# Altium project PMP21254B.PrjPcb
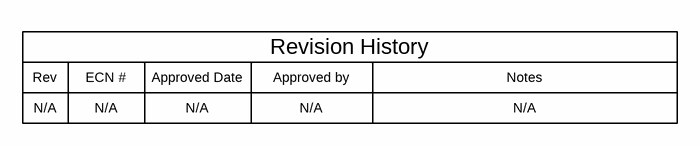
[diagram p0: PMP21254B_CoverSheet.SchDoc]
CopyrightYear: 2021; EVM_orderable: no; PCB_Layout: Josh Mandelcorn; PCB_Rev: B; PRJ_Customer: Public Release; PRJ_Engineer: Josh Mandelcorn; PRJ_Number: PMP21254; PRJ_Title: TPS546D24A 4 Phases Compact Design; SCH_Rev: B; TechSupport: http://www.ti.com/support; TID: N/A
3 sheets, 206 parts. Net scope: flat (ports and power ports of the same name join across sheets).
Board file: PMP21254B_PCB.PcbDoc
Sheets:
  PMP21254B_CoverSheet.SchDoc
  PMP21254B_Leader&Aux.SchDoc
  PMP21254B_Followers&Hardware.SchDoc

## Sheet PMP21254B_CoverSheet.SchDoc
size 431 x 279 mm; Date: Not shown in title block; ApprovedBy: Not shown in title block; CheckedBy: Not shown in title block; Author: Not shown in title block; CompanyName: Not shown in title block; Engineer: Not shown in title block; Organization: Not shown in title block; Address1: Not shown in title block; Address2: Not shown in title block; Address3: Not shown in title block; Address4: Not shown in title block; DocumentNumber: 1; Revision: Use project parameter SCH_Rev; SheetNumber: 1; SheetTotal: 3; PageSetup: Record=PageOptions¦CenterHorizontal=True¦CenterVertical=True¦PrintScale=1.00¦XCorrection=1.00¦YCorrection=1.00¦PrintKind=0¦BorderSize=5000000¦LeftOffset=0¦BottomOffset=0¦Orientation=2¦PaperLength=1000¦PaperWidth=1000¦Scale=100¦PaperSource=15¦PrintQuality=600¦MediaType=1¦DitherType=10¦PaperKind=Letter¦PrintScaleMode=1

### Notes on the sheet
- Rev
- N/A
- ECN #
- Approved Date
- Approved by
- Revision History
- Notes

## Sheet PMP21254B_Leader&Aux.SchDoc
size 431 x 279 mm; Date: Not shown in title block; ApprovedBy: Not shown in title block; CheckedBy: Not shown in title block; Author: Not shown in title block; CompanyName: Not shown in title block; Engineer: Not shown in title block; Organization: Not shown in title block; Address1: Not shown in title block; Address2: Not shown in title block; Address3: Not shown in title block; Address4: Not shown in title block; DocumentNumber: 1; Revision: Use project parameter SCH_Rev; SheetNumber: 2; SheetTotal: 3; PageSetup: Record=PageOptions¦CenterHorizontal=True¦CenterVertical=True¦PrintScale=1.00¦XCorrection=1.00¦YCorrection=1.00¦PrintKind=0¦BorderSize=5000000¦LeftOffset=0¦BottomOffset=0¦Orientation=2¦PaperLength=1000¦PaperWidth=1000¦Scale=100¦PaperSource=15¦PrintQuality=600¦MediaType=1¦DitherType=10¦PaperKind=Letter¦PrintScaleMode=1
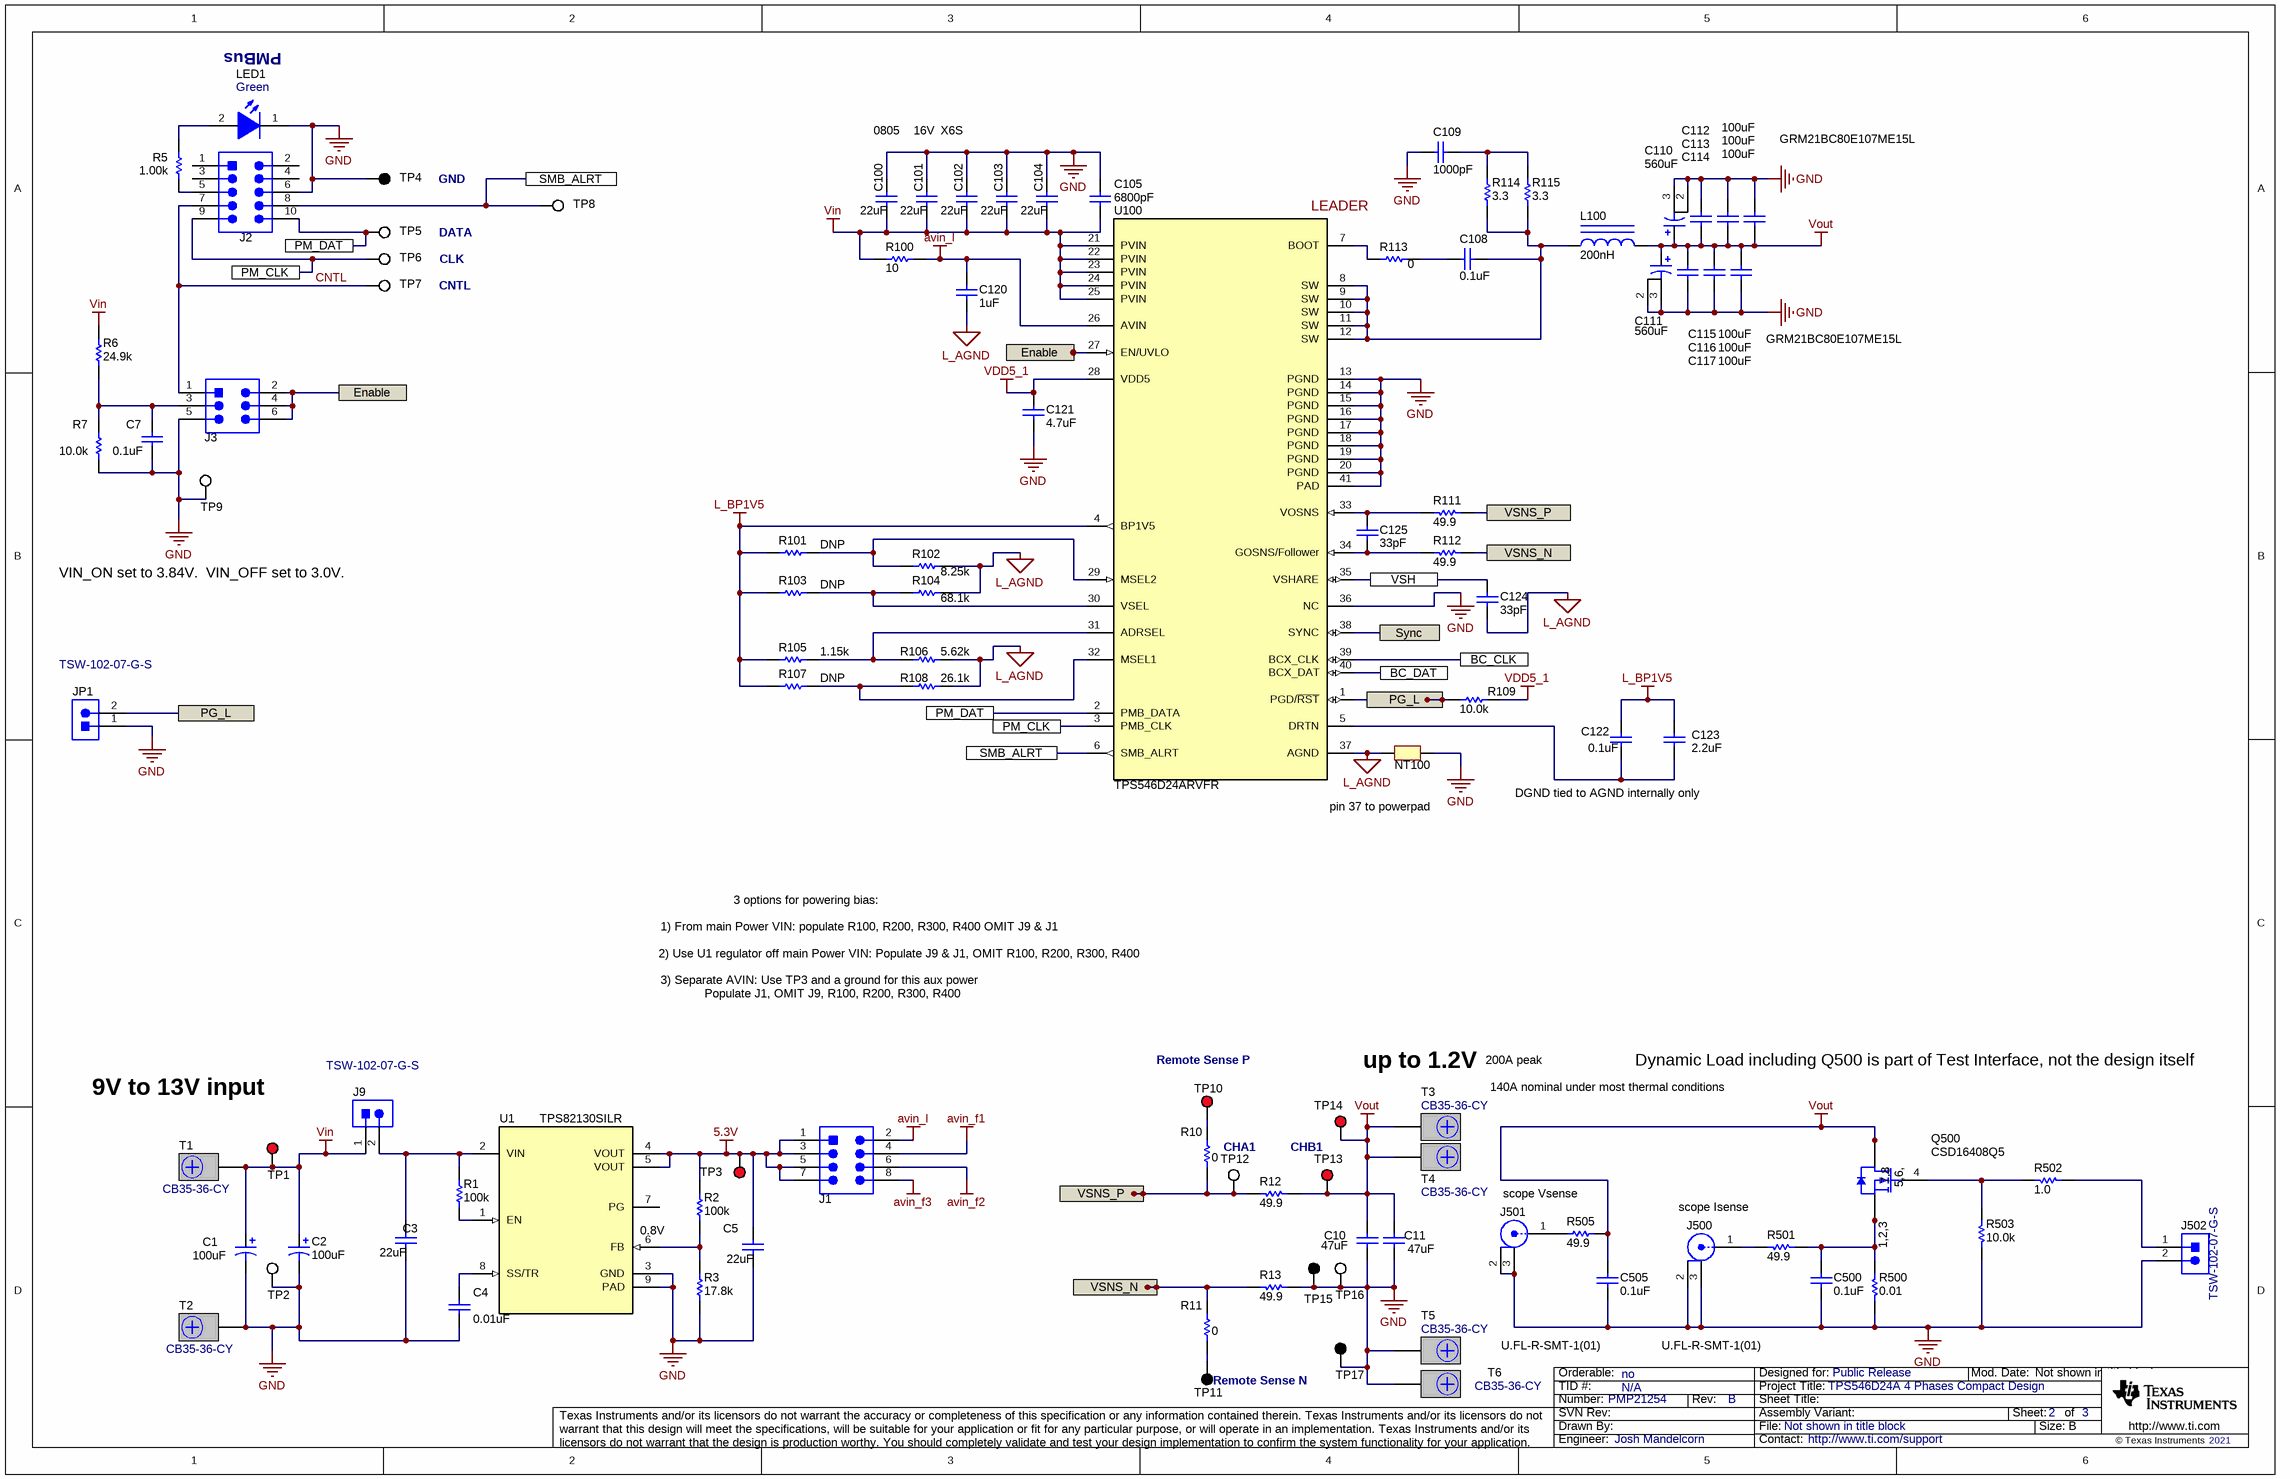
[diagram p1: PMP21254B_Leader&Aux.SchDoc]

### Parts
C1  ValueDisplayed: 100uF  [SM_RADIAL_G]  (hidden comment: Cap_Polarized)
C2  ValueDisplayed: 100uF  [SM_RADIAL_G]  (hidden comment: Cap_Polarized)
C3  value 22uF  [0805]  (hidden comment: Capacitor)
C4  ValueDisplayed: 0.01uF  [0402]  (hidden comment: C0402C103J5RACTU)
C5  value 22uF  [0805]  (hidden comment: Capacitor)
C7  ValueDisplayed: 0.1uF  [0402_065]  (hidden comment: Capacitor)
C10  ValueDisplayed: 47uF  [1210_270]  (hidden comment: Capacitor)
C11  ValueDisplayed: 47uF  [1210_270]  (hidden comment: Capacitor)
C100  value 22uF  [0805]  (hidden comment: Capacitor)
C101  value 22uF  VDC_V: 16V  TempCo: X6S  [0805]  (hidden comment: Capacitor)
C102  value 22uF  [0805]  (hidden comment: Capacitor)
C103  value 22uF  [0805]  (hidden comment: Capacitor)
C104  value 22uF  [0805]  (hidden comment: Capacitor)
C105  ValueDisplayed: 6800pF  [0402]  (hidden comment: Capacitor)
C108  ValueDisplayed: 0.1uF  [0402_065]  (hidden comment: Capacitor)
C109  ValueDisplayed: 1000pF  [0603L]  (hidden comment: Capacitor)
C110  ValueDisplayed: 560uF  [GX_3TERM]  (hidden comment: CAPP_POS1NEG23)
C111  ValueDisplayed: 560uF  [GX_3TERM]  (hidden comment: CAPP_POS1NEG23)
C112  ValueDisplayed: 100uF  [0805]  (hidden comment: Capacitor)
C113  ValueDisplayed: 100uF  [0805]  (hidden comment: Capacitor)
C114  ValueDisplayed: 100uF  [0805]  (hidden comment: Capacitor)
C115  ValueDisplayed: 100uF  [0805]  (hidden comment: Capacitor)
C116  ValueDisplayed: 100uF  [0805]  (hidden comment: Capacitor)
C117  ValueDisplayed: 100uF  [0805]  (hidden comment: Capacitor)
C120  ValueDisplayed: 1uF  [0603L]  (hidden comment: Capacitor)
C121  ValueDisplayed: 4.7uF  [0603]  (hidden comment: Capacitor)
C122  ValueDisplayed: 0.1uF  [0402_065]  (hidden comment: Capacitor)
C123  ValueDisplayed: 2.2uF  [0603L]  (hidden comment: Capacitor)
C124  ValueDisplayed: 33pF  [0402]  (hidden comment: Capacitor)
C125  ValueDisplayed: 33pF  [0402]  (hidden comment: Capacitor)
C500  ValueDisplayed: 0.1uF  [0402]  (hidden comment: Capacitor)
C505  ValueDisplayed: 0.1uF  [0402]  (hidden comment: Capacitor)
J1  Header_4x2  [CONN_PEC04DAAN]  (value not drawn)
J2  Header_5x2  [CONN_5103308-1]  (value not drawn)
J3  Header_3x2  [Sullins_PBC03DAAN]  (value not drawn)
J9  TSW-102-07-G-S  [TSW-102-07-G-S]
J500  U.FL-R-SMT-1(01)  [CONN_UFL-R-SMT-1]
J501  U.FL-R-SMT-1(01)  [CONN_UFL-R-SMT-1]
J502  TSW-102-07-G-S  [TSW-102-07-G-S]
JP1  TSW-102-07-G-S  [TSW-102-07-G-S]
L100  ValueDisplayed: 200nH  [SLC1480]  (hidden comment: SLC1480-201MLB)
LED1  value Green  [WL-SMCW_GREEN]  (hidden comment: 150060GS75000)
NT100  Net-Tie  [Net-Tie_10mil]  (value not drawn)  (net tie, no BOM)
Q500  CSD16408Q5  [DQH0008A]
R1  ValueDisplayed: 100k  [0402]  (hidden comment: ERJ-2RKF1003X)
R2  ValueDisplayed: 100k  [0402]  (hidden comment: ERJ-2RKF1003X)
R3  ValueDisplayed: 17.8k  [0402]  (hidden comment: CRCW040217K8FKED)
R5  ValueDisplayed: 1.00k  [0402]  (hidden comment: RC0402FR-071KL)
R6  ValueDisplayed: 24.9k  [0402]  (hidden comment: CRCW040224K9FKED)
R7  ValueDisplayed: 10.0k  [0402]  (hidden comment: RC0402FR-0710KL)
R10  ValueDisplayed: 0  [0402]  (hidden comment: CRCW04020000Z0ED)
R11  ValueDisplayed: 0  [0402]  (hidden comment: CRCW04020000Z0ED)
R12  ValueDisplayed: 49.9  [0402]  (hidden comment: Resistor)
R13  ValueDisplayed: 49.9  [0402]  (hidden comment: Resistor)
R100  ValueDisplayed: 10  [0402]  (hidden comment: CRCW040210R0JNED)
R101  ValueDisplayed: DNP  [0402]  (hidden comment: Resistor)
R102  ValueDisplayed: 8.25k  [0402]  (hidden comment: Resistor)
R103  ValueDisplayed: DNP  [0402]  (hidden comment: Resistor)
R104  ValueDisplayed: 68.1k  [0402]  (hidden comment: Resistor)
R105  ValueDisplayed: 1.15k  [0402]  (hidden comment: Resistor)
R106  ValueDisplayed: 5.62k  [0402]  (hidden comment: Resistor)
R107  ValueDisplayed: DNP  [0402]  (hidden comment: Resistor)
R108  ValueDisplayed: 26.1k  [0402]  (hidden comment: Resistor)
R109  ValueDisplayed: 10.0k  [0402]  (hidden comment: Resistor)
R111  ValueDisplayed: 49.9  [0402]  (hidden comment: Resistor)
R112  ValueDisplayed: 49.9  [0402]  (hidden comment: Resistor)
R113  ValueDisplayed: 0  [0402]  (hidden comment: Resistor)
R114  ValueDisplayed: 3.3  [0805]  (hidden comment: Resistor)
R115  ValueDisplayed: 3.3  [0805]  (hidden comment: Resistor)
R500  ValueDisplayed: 0.01  [2512]  (hidden comment: Resistor)
R501  ValueDisplayed: 49.9  [0402]  (hidden comment: Resistor)
R502  ValueDisplayed: 1.0  [0402]  (hidden comment: Resistor)
R503  ValueDisplayed: 10.0k  [0402]  (hidden comment: Resistor)
R505  ValueDisplayed: 49.9  [0402]  (hidden comment: Resistor)
T1  CB35-36-CY  [CB35-36-CY]
T2  CB35-36-CY  [CB35-36-CY]
T3  CB35-36-CY  [CB35-36-CY]
T4  CB35-36-CY  [CB35-36-CY]
T5  CB35-36-CY  [CB35-36-CY]
T6  CB35-36-CY  [CB35-36-CY]
TP1  5000  [Keystone5000]  (value not drawn)
TP2  5016  [Testpoint_Keystone_Compact]  (value not drawn)
TP3  5000  [Keystone5000]  (value not drawn)
TP4  5011  [Keystone5011]  (value not drawn)
TP5  5012  [Keystone5012]  (value not drawn)
TP6  5012  [Keystone5012]  (value not drawn)
TP7  5012  [Keystone5012]  (value not drawn)
TP8  5012  [Keystone5012]  (value not drawn)
TP9  5016  [Testpoint_Keystone_Compact]  (value not drawn)
TP10  5010  [Keystone5010]  (value not drawn)
TP11  5011  [Keystone5011]  (value not drawn)
TP12  5012  [Keystone5012]  (value not drawn)
TP13  5010  [Keystone5010]  (value not drawn)
TP14  5010  [Keystone5010]  (value not drawn)
TP15  5011  [Keystone5011]  (value not drawn)
TP16  5016  [Testpoint_Keystone_Compact]  (value not drawn)
TP17  5001  [Keystone5001]  (value not drawn)
U1  TPS82130SILR  [SIL0008D_SMD]
U100  TPS546D24ARVFR  [RVF0040A_SMD_NV]

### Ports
BC_CLK, BC_DAT, Enable, PG_L, PM_CLK, PM_DAT, SMB_ALRT, Sync, VSH, VSNS_N, VSNS_P

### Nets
5.3V: C5.1 J1.1 J1.3 J1.5 J1.7 R2.2 TP3.1 U1.4(VOUT) U1.5(VOUT)
avin_f1: J1.4
avin_f2: J1.6
avin_f3: J1.8
avin_l: C120.1 J1.2 R100.2 U100.26(AVIN)
GND: C1.2(-) C2.2(-) C3.2 C4.2 C5.2 C7.1 C10.1 C11.1 C100.1 C101.1 C102.1 C103.1 C104.1 C105.2 C109.2 C110.2(-) C110.3(-) C111.2(-) C111.3(-) C112.2 C113.2 C114.2 C115.2 C116.2 C117.2 C121.1 C500.2 C505.2 J2.6 J3.5 J500.2 J500.3 J501.2 J501.3 J502.2 JP1.1 LED1.1(K) NT100.2 R3.1 R7.1 R13.1 R500.1 R503.1 T2.1 T5.1 T6.1 TP2.1 TP4.1 TP9.1 TP15.1 TP16.1 TP17.1 U1.3(GND) U1.9(PAD) U100.13(PGND) U100.14(PGND) U100.15(PGND) U100.16(PGND) U100.17(PGND) U100.18(PGND) U100.19(PGND) U100.20(PGND) U100.36(NC) U100.41(PAD)
L_AGND: C120.2 C124.2 NT100.1 R102.2 R104.2 R106.2 R108.2 U100.37(AGND)
L_BP1V5: C122.1 C123.1 R101.1 R103.1 R105.1 R107.1 U100.4(BP1V5)
VDD5_1: C121.2 R109.1 U100.28(VDD5)
Vin: C1.1(+) C2.1(+) C100.2 C101.2 C102.2 C103.2 C104.2 C105.1 J9.1 R6.2 R100.1 T1.1 TP1.1 U100.21(PVIN) U100.22(PVIN) U100.23(PVIN) U100.24(PVIN) U100.25(PVIN)
Vout: C10.2 C11.2 C110.1(+) C111.1(+) C112.1 C113.1 C114.1 C115.1 C116.1 C117.1 C505.1 L100.2 Q500.5(D) Q500.6(D) Q500.7(D) Q500.8(D) Q500.9(D) R12.1 R505.2 T3.1 T4.1 TP13.1 TP14.1
BC_CLK: U100.39(BCX_CLK) ; port BC_CLK
BC_DAT: U100.40(BCX_DAT) ; port BC_DAT
CNTL: J2.7 J3.1 TP7.1
Enable: J3.2 J3.4 J3.6 U100.27(EN/UVLO) ; port Enable
PG_L: JP1.2 R109.2 U100.1(PGD/~{RST}) ; port PG_L
PM_CLK: J2.9 TP6.1 U100.3(PMB_CLK) ; port PM_CLK
PM_DAT: J2.10 TP5.1 U100.2(PMB_DATA) ; port PM_DAT
SMB_ALRT: J2.8 TP8.1 U100.6(SMB_ALRT) ; port SMB_ALRT
Sync: U100.38(SYNC) ; port Sync
VSH: C124.1 U100.35(VSHARE) ; port VSH
VSNS_N: R11.2 R13.2 R112.1 ; port VSNS_N
VSNS_P: R10.1 R12.2 R111.1 TP12.1 ; port VSNS_P
NetC3_1: C3.1 J9.2 R1.2 U1.2(VIN)
NetC4_1: C4.1 U1.8(SS/TR)
NetC7_2: C7.2 J3.3 R6.1 R7.2
NetC108_1: C108.1 R113.1
NetC108_2: C108.2 L100.1 R114.1 R115.1 U100.8(SW) U100.9(SW) U100.10(SW) U100.11(SW) U100.12(SW)
NetC109_1: C109.1 R114.2 R115.2
NetC122_2: C122.2 C123.2 U100.5(DRTN)
NetC125_1: C125.1 R111.2 U100.33(VOSNS)
NetC125_2: C125.2 R112.2 U100.34(GOSNS/Follower)
NetC500_1: C500.1 Q500.1(S) Q500.2(S) Q500.3(S) R500.2 R501.1
NetJ2_5: J2.5 R5.1
NetJ500_1: J500.1 R501.2
NetJ501_1: J501.1 R505.1
NetJ502_1: J502.1 R502.1
NetLED1_2: LED1.2(A) R5.2
NetQ500_4: Q500.4(G) R502.2 R503.2
NetR1_1: R1.1 U1.1(EN)
NetR2_1: R2.1 R3.2 U1.6(FB)
NetR10_2: R10.2 TP10.1
NetR11_1: R11.1 TP11.1
NetR101_2: R101.2 R102.1 U100.29(MSEL2)
NetR103_2: R103.2 R104.1 U100.30(VSEL)
NetR105_2: R105.2 R106.1 U100.31(ADRSEL)
NetR107_2: R107.2 R108.1 U100.32(MSEL1)
NetR113_2: R113.2 U100.7(BOOT)

Not connected (* = marked no-connect by the designer): J2 1 2 3 4; U1 7(PG)

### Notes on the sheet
- PMBus
- GRM21BC80E107ME15L
- GND
- DATA
- LEADER
- CLK
- CNTL
- VIN_ON set to 3.84V.  VIN_OFF set to 3.0V.
- pin 37 to powerpad
- DGND tied to AGND internally only
- 3 options for powering bias:
- 1) From main Power VIN: populate R100, R200, R300, R400 OMIT J9 & J1
- 2) Use U1 regulator off main Power VIN: Populate J9 & J1, OMIT R100, R200, R300, R400
- 3) Separate AVIN: Use TP3 and a ground for this aux power
- Populate J1, OMIT J9, R100, R200, R300, R400
- 9V to 13V input
- (near TP10) Remote Sense P
- up to 1.2V
- 200A peak
- 140A nominal under most thermal conditions
- Dynamic Load including Q500 is part of Test Interface, not the design itself
- CHA1
- CHB1
- (near U1) 0.8V
- scope Vsense
- scope Isense
- (near TP11) Remote Sense N

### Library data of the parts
C1 C2 = CMP-0010663-1: CAP, AL, 100 uF, 35 V, +/- 20%, 0.15 ohm, SMD; PartNumber: EEE-FC1V101P; Manufacturer: Panasonic; Polarized: Y; CompType: Capacitor; Value: 100uF; U/M: EA; Cap_F: 100µF; ESR_ohm: 1.5d; VDC_V: 35V; IRMS_A: 2.2dA; TaMin_C: -40°C; TaMax_C: 105°C; Cap_Case: G; AEC Category: Q200; SizeArea_mm2: 123.6; SizeAreaWB_mm2: 172.2; SizeX_mm: 12; SizeY_mm: 10.3; SizeZ_mm: 10.2
C3 C5 C100 C102-C104 = CMP-0007852-1: CAP, CERM, 22 uF, 16 V, +/- 20%, X6S, 0805; PartNumber: C2012X6S1C226M125AC; Manufacturer: TDK; Polarized: N; U/M: EA; Cap_F: 22µF; ESR_ohm: 2.05m; Value1: 0.00205 ohm; VDC_V: 16V; IRMS_A: 4.55587A; TaMin_C: -55°C; TaMax_C: 105°C; SizeArea_mm2: 2.5; SizeAreaWB_mm2: 6.75; SizeX_mm: 2; SizeY_mm: 1.25; SizeZ_mm: 1.45; AEC Category: Q200
C4 = CMP-0006236-2: CAP, CERM, 0.01 uF, 50 V, +/- 5%, X7R, 0402; Manufacturer: Kemet; TaMin_C: -55°C; Polarized: N; SizeAreaWB_mm2: 3; Value1: Unknown; U/M: EA; Value: 0.01uF; TaMax_C: 125°C; SizeZ_mm: 0.6; SizeX_mm: 1; SizeY_mm: 0.5; Value2: 50V; CompType: Capacitor; Cap_F: 10nF; AEC Category: Q200
C7 C108 C122 = CMP-0006204-2: CAP, CERM, 0.1 uF, 16 V, +/- 10%, X5R, 0402; PartNumber: 160R07X104KV4T; Manufacturer: Johanson Technology; Polarized: N; Value: 0.1uF; U/M: EA; Cap_F: 100nF; Value1: Unknown; VDC_V: 16V; TaMin_C: -55°C; TaMax_C: 85°C; Cap_Case: 0402; SizeArea_mm2: 0.5; SizeAreaWB_mm2: 3; SizeX_mm: 1; SizeZ_mm: 0.65; AEC Category: Q200
C10 C11 = CMP-0009220-2: CAP, CERM, 47 uF, 10 V, +/- 10%, X7R, 1210; PartNumber: GRM32ER71A476KE15L; Manufacturer: MuRata; U/M: EA; Cap_F: 47µF; Value: 47uF; Value1: Unknown; VDC_V: 10V; TaMin_C: -55°C; TaMax_C: 125°C; Polarized: N; Cap_Case: 1210; SizeArea_mm2: 8; SizeAreaWB_mm2: 14.7; SizeX_mm: 3.2; SizeY_mm: 2.5; SizeZ_mm: 2.7; AEC Category: Q200
C101 = CMP-0007852-1: CAP, CERM, 22 uF, 16 V, +/- 20%, X6S, 0805; PartNumber: C2012X6S1C226M125AC; Manufacturer: TDK; Polarized: N; U/M: EA; Cap_F: 22µF; ESR_ohm: 2.05m; Value1: 0.00205 ohm; IRMS_A: 4.55587A; TaMin_C: -55°C; TaMax_C: 105°C; SizeArea_mm2: 2.5; SizeAreaWB_mm2: 6.75; SizeX_mm: 2; SizeY_mm: 1.25; SizeZ_mm: 1.45; AEC Category: Q200
C105 = CMP-0006696-2: CAP, CERM, 6800 pF, 50 V, +/- 10%, X7R, 0402; PartNumber: GRM155R71H682KA88D; Manufacturer: MuRata; Polarized: N; Value: 6800pF; U/M: EA; Cap_F: 6.8nF; Value1: Unknown; VDC_V: 50V; TaMin_C: -55°C; TaMax_C: 125°C; AEC Category: Q200; SizeArea_mm2: 0.5; SizeAreaWB_mm2: 3; SizeX_mm: 1; SizeZ_mm: 0.6
C109 = CMP-0006723-4: CAP, CERM, 1000 pF, 100 V, +/- 5%, X7R, 0603; PartNumber: 06031C102JAT2A; Manufacturer: AVX; Polarized: N; Value: 1000pF; U/M: EA; Cap_F: 1nF; ESR_ohm: 2.76d; Value1: 0.276 ohm; VDC_V: 100V; TaMin_C: -55°C; TaMax_C: 125°C; Cap_Case: 0603; AEC Category: Q200; SizeArea_mm2: 1.28; SizeAreaWB_mm2: 4.68; SizeX_mm: 1.6; SizeY_mm: 0.8; SizeZ_mm: 1
C110 C111 = CMP-0012239-3: CAP, Aluminum Polymer, 560 uF, 2 V, +/- 20%, 0.003 ohm, SMD_7.3x1.9x4.3mm SMD; Manufacturer: Panasonic; PartNumber: EEF-GX0D561L; CompType: Capacitor; Value: 560uF; Polarized: Y; Cap_F: 560µF; VDC_V: 2V; ESR_ohm: 3m; IRMS_A: 4A; TaMin_C: -40°C; TaMax_C: 105°C; Cap_Case: D; SizeAreaWB_mm2: 58.59; SizeArea_mm2: 31.39; SizeX_mm: 7.3; SizeY_mm: 4.3; SizeZ_mm: 2; AEC Category: Q200; AEC Qualified: N
C112-C117 = CMP-0008277-2: CAP, CERM, 100 uF, 4 V, +/- 20%, X5R, 0805; PartNumber: GRM21BR60G107ME15L; Manufacturer: MuRata; U/M: EA; Cap_F: 100µF; Value: 100uF; Value1: Unknown; VDC_V: 4V; TaMin_C: -55°C; TaMax_C: 85°C; Polarized: N; SizeArea_mm2: 2.5; SizeAreaWB_mm2: 6.75; SizeX_mm: 2; SizeY_mm: 1.25; SizeZ_mm: 1.45; AEC Category: Q200
C120 = CMP-0007405-4: CAP, CERM, 1 uF, 25 V, +/- 10%, X7R, 0603; PartNumber: GRM188R71E105KA12D; Manufacturer: MuRata; Polarized: N; Value: 1uF; U/M: EA; Cap_F: 1µF; Value1: Unknown; VDC_V: 25V; TaMin_C: -55°C; TaMax_C: 125°C; Cap_Case: 0603; AEC Category: Q200; SizeArea_mm2: 1.28; SizeAreaWB_mm2: 4.68; SizeX_mm: 1.6; SizeY_mm: 0.8; SizeZ_mm: 1
C121 = CMP-0007058-4: CAP, CERM, 4.7 uF, 10 V, +/- 10%, X7S, 0603; PartNumber: C1608X7S1A475K080AC; Manufacturer: TDK; Polarized: N; Value: 4.7uF; U/M: EA; Cap_F: 4.7µF; Value1: Unknown; VDC_V: 10V; TaMin_C: -55°C; TaMax_C: 125°C; SizeArea_mm2: 1.28; SizeAreaWB_mm2: 4.68; SizeX_mm: 1.6; SizeY_mm: 0.8; SizeZ_mm: 1; AEC Category: Q200
C123 = CMP-0007499-4: CAP, CERM, 2.2 uF, 16 V, +/- 10%, X7R, 0603; PartNumber: GRM188Z71C225KE43; Manufacturer: MuRata; Polarized: N; Value: 2.2uF; U/M: EA; Cap_F: 2.2µF; Value1: Unknown; VDC_V: 16V; TaMin_C: -55°C; TaMax_C: 125°C; Cap_Case: 0603; SizeArea_mm2: 1.28; SizeAreaWB_mm2: 4.68; SizeX_mm: 1.6; SizeY_mm: 0.8; SizeZ_mm: 1; AEC Category: Q200
C124 C125 = CMP-0006377-2: CAP, CERM, 33 pF, 25 V, +/- 5%, C0G/NP0, 0402; PartNumber: GRM1555C1E330JA01D; Manufacturer: MuRata; Polarized: N; Value: 33pF; U/M: EA; Value1: Unknown; VDC_V: 25V; TaMin_C: -55°C; TaMax_C: 125°C; SizeArea_mm2: 0.5; SizeAreaWB_mm2: 3; SizeX_mm: 1; SizeZ_mm: 0.6; AEC Category: Q200
C500 = CMP-0006607-2: CAP, CERM, 0.1 uF, 25 V, +/- 10%, X5R, 0402; PartNumber: GRM155R61E104KA87D; Manufacturer: MuRata; Polarized: N; Value: 0.1uF; U/M: EA; Cap_F: 100nF; Value1: Unknown; VDC_V: 25V; TaMin_C: -55°C; TaMax_C: 85°C; AEC Category: Q200; SizeArea_mm2: 0.5; SizeAreaWB_mm2: 3; SizeX_mm: 1; SizeZ_mm: 0.6
C505 = CMP-0006607-2: CAP, CERM, 0.1 uF, 25 V, +/- 10%, X5R, 0402; PartNumber: GRM155R61E104KA87D; Manufacturer: MuRata; Polarized: N; Value: 0.1uF; U/M: EA; Cap_F: 100nF; Value1: Unknown; VDC_V: 25V; TaMin_C: -55°C; TaMax_C: 85°C; SizeArea_mm2: 0.5; SizeAreaWB_mm2: 3; SizeX_mm: 1; SizeZ_mm: 0.6; AEC Category: Q200
J1 = CMP-0054542-2: Header, 100mil, 4x2, Tin, TH; PartNumber: PEC04DAAN; Manufacturer: Sullins Connector Solutions; Pitch_mm: 2.54; Gender: Male; Shrouded: N; Row_Count: 2; Current_A: 3A; Voltage_V: 1.8kV; Cert_UL: Y; Green_Lifecycle: Not Set; Green_REACh: Incomplete
J2 = CMP-0054834-2: Header (shrouded), 100mil, 5x2, Gold, TH; PartNumber: 5103308-1; Manufacturer: TE Connectivity; Green_Lifecycle: Active; Green_REACh: Passed
J3 = CMP-0054565-2: Header, 100mil, 3x2, Gold, TH; PartNumber: PBC03DAAN; Manufacturer: Sullins Connector Solutions; Pitch_mm: 2.54; Gender: Male; Shrouded: N; Row_Count: 2; Current_A: 3A; Voltage_V: 1.8kV; Cert_UL: Y; Green_Lifecycle: Active; Green_REACh: Passed
J9 J502 JP1 = CMP-0075405-3: Header, 100mil, 2x1, Gold, TH; Manufacturer: Samtec; Pitch_mm: 2.54; Gender: Male; Shrouded: N; Row_Count: 1; Current_A: 6.3A; Voltage_V: 550V; Cert_CSA: Y; Green_Lifecycle: Active; Green_REACh: Passed
J500 J501 = CMP-0075320-1: Receptacle, Ultra Miniature Coaxial, Male Pin, 50 ohm, SMT; Manufacturer: Hirose Electric Co. Ltd.; CNHeader: False; Gender: Female; ContactFinish: Gold
L100 = CMP-0060886-1: Inductor, Shielded, Ferrite, 200 nH, 55 A, 0.00015 ohm, SMD; Manufacturer: Coilcraft; Isat: 76A @ 30% inductance drop; Irms: 55A @ 40C rise; Green_Lifecycle: Not Set; SizeAreaWB_mm2: 231.127; DCR_ohm: 150µ; Green_REACh: Incomplete; Value: 200nH; Imax_A: 55A; SizeZ_mm: 8; SizeY_mm: 12.95; SizeArea_mm2: 174.307; AEC Category: Q200; SizeX_mm: 13.46
LED1 = CMP-0002905-2: LED, Green, SMD; Manufacturer: Wurth Elektronik; Type: InGaN; Vf_V: 3.2V; Io_A: 20mA; Tjmax_C: 85°C; Value1: W; Angle: 140
NT100 = CMP-0078142-3: Single point connection between nets.
Q500 = CMP-0000264-1: MOSFET, N-CH, 25 V, 113 A, DQH0008A (VSON-CLIP-8); Manufacturer: Texas Instruments; Alternate Manufacturer: None; U/M: EA; ChType: N; Value: 25V; Value1: 0.005; Rdson45_ohm: 5.4m; Value2: 6.7 nC; QgTyp_nC: 6.7; Vgs_V: 16V; IdsMax_A: 113A; SizeAreaWB_mm2: 56; SizeArea_mm2: 30; SizeX_mm: 6; SizeY_mm: 5; SizeZ_mm: 1.05; AEC Category: Q101
R1 R2 = CMP-0026659-1: RES, 100 k, 1%, 0.1 W, 0402; Manufacturer: Panasonic; Power_W: 100mW; TempCo: 100 ppm/C; U/M: EA; Value: 100k; EIA_Code: E96; SizeX_mm: 1; SizeY_mm: 0.5; SizeZ_mm: 0.6; Value2: 0.1W; VDC_V: 50V; AEC Category: Q200
R3 = CMP-0026051-3: RES, 17.8 k, 1%, 0.063 W, AEC-Q200 Grade 0, 0402; Manufacturer: Vishay-Dale; Power_W: 63mW; TempCo: 100 ppm/C; Value_Code: 17k8; Value: 17.8k; EIA_Code: E96; SizeX_mm: 1; SizeY_mm: 0.5; SizeZ_mm: 0.6; Value2: 0.063W; AEC Qualified: Y; VDC_V: 50V; AEC Category: Q200; AEC Grade: 0
R5 = CMP-0026725-1: RES, 1.00 k, 1%, 0.0625 W, 0402; Manufacturer: Yageo America; Power_W: 62.5mW; TempCo: 100 ppm/C; Value_Code: 1k00; U/M: EA; Value: 1.00k; EIA_Code: E96; Res_ohm: 1k; SizeX_mm: 1; SizeY_mm: 0.5; SizeZ_mm: 0.6; AEC Qualified: N; VDC_V: 50V; AEC Category: Q200
R6 = CMP-0026196-2: RES, 24.9 k, 1%, 0.063 W, AEC-Q200 Grade 0, 0402; Manufacturer: Vishay-Dale; Power_W: 63mW; TempCo: 100 ppm/C; Value_Code: 24k9; Value: 24.9k; EIA_Code: E96; SizeX_mm: 1; SizeY_mm: 0.5; SizeZ_mm: 0.6; Value2: 0.063W; AEC Qualified: Y; VDC_V: 50V; AEC Category: Q200; AEC Grade: 0
R7 = CMP-0078669-1: RES, 10.0 k, 1%, 0.063 W, 0402; Manufacturer: Yageo America; Power_W: 63mW; Green_Lifecycle: Active; TempCo: 100 ppm/C; Value_Code: 10k0; Green_REACh: Passed; Value: 10.0k; EIA_Code: E96; Res_ohm: 10k; SizeX_mm: 1; SizeY_mm: 0.5; SizeZ_mm: 0.6; Value2: 0.063W; AEC Qualified: N; AEC Category: Q200
R10 R11 = CMP-0026822-3: RES, 0, 5%, 0.063 W, AEC-Q200 Grade 0, 0402; Manufacturer: Vishay-Dale; Power_W: 63mW; TempCo: 200 ppm/C; Value_Code: 0000; Value: 0; EIA_Code: E24; SizeX_mm: 1; SizeY_mm: 0.5; SizeZ_mm: 0.6; Value2: 0.063W; AEC Qualified: Y; VDC_V: 50V; AEC Category: Q200
R12 R13 R111 R112 R501 = CMP-0026404-2: RES, 49.9, 1%, 0.063 W, AEC-Q200 Grade 0, 0402; PartNumber: CRCW040249R9FKED; Manufacturer: Vishay-Dale; Value: 49.9; Value_Code: 49R9; Power_W: 63mW; Value2: 0.063W; VDC_V: 50V; TempCo: 100 ppm/C; EIA_Code: E96; AEC Category: Q200; AEC Qualified: Y; AEC Grade: 0; SizeArea_mm2: 0.5; SizeX_mm: 1; SizeZ_mm: 0.6
R100 = CMP-0026827-3: RES, 10, 5%, 0.063 W, AEC-Q200 Grade 0, 0402; Manufacturer: Vishay-Dale; Power_W: 63mW; TempCo: 200 ppm/C; Value_Code: 10R0; Value: 10; EIA_Code: E24; SizeX_mm: 1; SizeY_mm: 0.5; SizeZ_mm: 0.6; Value2: 0.063W; AEC Qualified: Y; VDC_V: 50V; AEC Category: Q200; AEC Grade: 0
R101-R109 = CMP-0025958-3: RES, 10.0 k, 1%, 0.063 W, AEC-Q200 Grade 0, 0402; PartNumber: CRCW040210K0FKED; Manufacturer: Vishay-Dale; Value: 10.0k; Res_ohm: 10k; Value_Code: 10k0; Power_W: 63mW; Value2: 0.063W; VDC_V: 50V; TempCo: 100 ppm/C; EIA_Code: E96; SizeArea_mm2: 0.5; SizeX_mm: 1; SizeZ_mm: 0.6; AEC Category: Q200; AEC Qualified: Y; AEC Grade: 0
R113 = CMP-0026822-3: RES, 0, 5%, 0.063 W, AEC-Q200 Grade 0, 0402; PartNumber: CRCW04020000Z0ED; Manufacturer: Vishay-Dale; Value: 0; Value_Code: 0000; Power_W: 63mW; Value2: 0.063W; VDC_V: 50V; TempCo: 200 ppm/C; EIA_Code: E24; SizeArea_mm2: 0.5; SizeX_mm: 1; SizeZ_mm: 0.6; AEC Category: Q200; AEC Qualified: Y
R114 R115 = CMP-0020547-3: RES, 3.3, 5%, 0.125 W, AEC-Q200 Grade 0, 0805; PartNumber: CRCW08053R30JNEA; Manufacturer: Vishay-Dale; Value: 3.3; Value_Code: 3R30; Power_W: 125mW; Value2: 0.125W; VDC_V: 150V; TempCo: 200 ppm/C; SizeArea_mm2: 2.5; SizeX_mm: 2; SizeY_mm: 1.25; SizeZ_mm: 1.45; EIA_Code: E24; AEC Category: Q200; AEC Qualified: Y; AEC Grade: 0
R500 = CMP-0015807-2: RES, 0.01, 1%, 1 W, 2512; PartNumber: ERJ-M1WSF10MU; Manufacturer: Panasonic; Value: 0.01; Value_Code: R010; Power_W: 1W; TempCo: 100 ppm/C; EIA_Code: E96; U/M: EA; AEC Category: Q200; SizeArea_mm2: 20.16; SizeX_mm: 6.3; SizeY_mm: 3.2; SizeZ_mm: 0.71
R502 = CMP-0026866-3: RES, 1.0, 5%, 0.063 W, AEC-Q200 Grade 0, 0402; PartNumber: CRCW04021R00JNED; Manufacturer: Vishay-Dale; Value: 1.0; Res_ohm: 1; Value_Code: 1R00; Power_W: 63mW; Value2: 0.063W; VDC_V: 50V; TempCo: 200 ppm/C; EIA_Code: E24; AEC Category: Q200; AEC Qualified: Y; AEC Grade: 0; SizeArea_mm2: 0.5; SizeZ_mm: 0.6
R503 = CMP-0025958-3: RES, 10.0 k, 1%, 0.063 W, AEC-Q200 Grade 0, 0402; PartNumber: CRCW040210K0FKED; Manufacturer: Vishay-Dale; Value: 10.0k; Res_ohm: 10k; Value_Code: 10k0; Power_W: 63mW; Value2: 0.063W; VDC_V: 50V; TempCo: 100 ppm/C; EIA_Code: E96; AEC Category: Q200; AEC Qualified: Y; AEC Grade: 0; SizeArea_mm2: 0.5; SizeX_mm: 1; SizeZ_mm: 0.6
R505 = CMP-0026404-2: RES, 49.9, 1%, 0.063 W, AEC-Q200 Grade 0, 0402; PartNumber: CRCW040249R9FKED; Manufacturer: Vishay-Dale; Value: 49.9; Value_Code: 49R9; Power_W: 63mW; Value2: 0.063W; VDC_V: 50V; TempCo: 100 ppm/C; EIA_Code: E96; SizeArea_mm2: 0.5; SizeX_mm: 1; SizeZ_mm: 0.6; AEC Category: Q200; AEC Qualified: Y; AEC Grade: 0
T1-T6 = CMP-0055442-1: Terminal 50A Lug; Manufacturer: Panduit; CompType: Screw Terminal; ContactFinish: Copper; Voltage_V: 600V; Cert_CULUS: Y; CNHeader: FALSE; Green_Lifecycle: Not Set; Green_REACh: Incomplete
TP1 TP3 = CMP-0055137-1: Test Point, Miniature, Red, TH; Manufacturer: Keystone; ContactFinish: Silver; Green_Lifecycle: Active; Green_REACh: Passed; CNHeader: FALSE; CT: TRUE
TP2 TP9 TP16 = CMP-0055153-1: Test Point, Compact, SMT; Manufacturer: Keystone; Green_Lifecycle: Active; Green_REACh: Passed; CNHeader: FALSE; CT: TRUE
TP4 TP11 TP15 = CMP-0055148-1: Test Point, Multipurpose, Black, TH; Manufacturer: Keystone; ContactFinish: Silver; CNHeader: FALSE; CT: TRUE; Green_Lifecycle: Active; Green_REACh: Passed
TP5-TP8 TP12 = CMP-0055149-1: Test Point, Multipurpose, White, TH; Manufacturer: Keystone; ContactFinish: Silver; CNHeader: FALSE; CT: TRUE; Green_Lifecycle: Active; Green_REACh: Passed
TP10 TP13 TP14 = CMP-0055147-1: Test Point, Multipurpose, Red, TH; Manufacturer: Keystone; ContactFinish: Silver; CNHeader: FALSE; CT: TRUE; Green_Lifecycle: Active; Green_REACh: Passed
TP17 = CMP-0055138-1: Test Point, Miniature, Black, TH; Manufacturer: Keystone; ContactFinish: Silver; Green_Lifecycle: Active; Green_REACh: Passed; CNHeader: FALSE; CT: TRUE
U1 = CMP-0074206-2: 3-A 17V Step-down Converter Module with Integrated Inductor, SIL0008D (uSIP-8); Alternate PartNumber: TPS82130SILT; Alternate Manufacturer: Texas Instruments; SizeAreaWB_mm2: 15.2; SizeZ_mm: 1.53; SizeX_mm: 2.8; SizeY_mm: 3; SizeArea_mm2: 8.4; CompType: IC; AEC Category: Q200; AEC Qualified: N
U100 = CMP-0860534-2: 2.95-16V 40A PMBUS Stackable Synchronous Buck Converter, RVF0040A (LQFN-CLIP-40); Alternate Manufacturer: Texas Instruments; AEC Qualified: N; SizeAreaWB_mm2: 63; CompType: IC; SizeZ_mm: 1.52; AEC Category: Q200; SizeY_mm: 7; SizeArea_mm2: 35; SizeX_mm: 5

## Sheet PMP21254B_Followers&Hardware.SchDoc
size 431 x 279 mm; Date: Not shown in title block; ApprovedBy: Not shown in title block; CheckedBy: Not shown in title block; Author: Not shown in title block; CompanyName: Not shown in title block; Engineer: Not shown in title block; Organization: Not shown in title block; Address1: Not shown in title block; Address2: Not shown in title block; Address3: Not shown in title block; Address4: Not shown in title block; DocumentNumber: 1; Revision: Use project parameter SCH_Rev; SheetNumber: 3; SheetTotal: 3; PageSetup: Record=PageOptions¦CenterHorizontal=True¦CenterVertical=True¦PrintScale=1.00¦XCorrection=1.00¦YCorrection=1.00¦PrintKind=0¦BorderSize=5000000¦LeftOffset=0¦BottomOffset=0¦Orientation=2¦PaperLength=1000¦PaperWidth=1000¦Scale=100¦PaperSource=15¦PrintQuality=600¦MediaType=1¦DitherType=10¦PaperKind=Letter¦PrintScaleMode=1
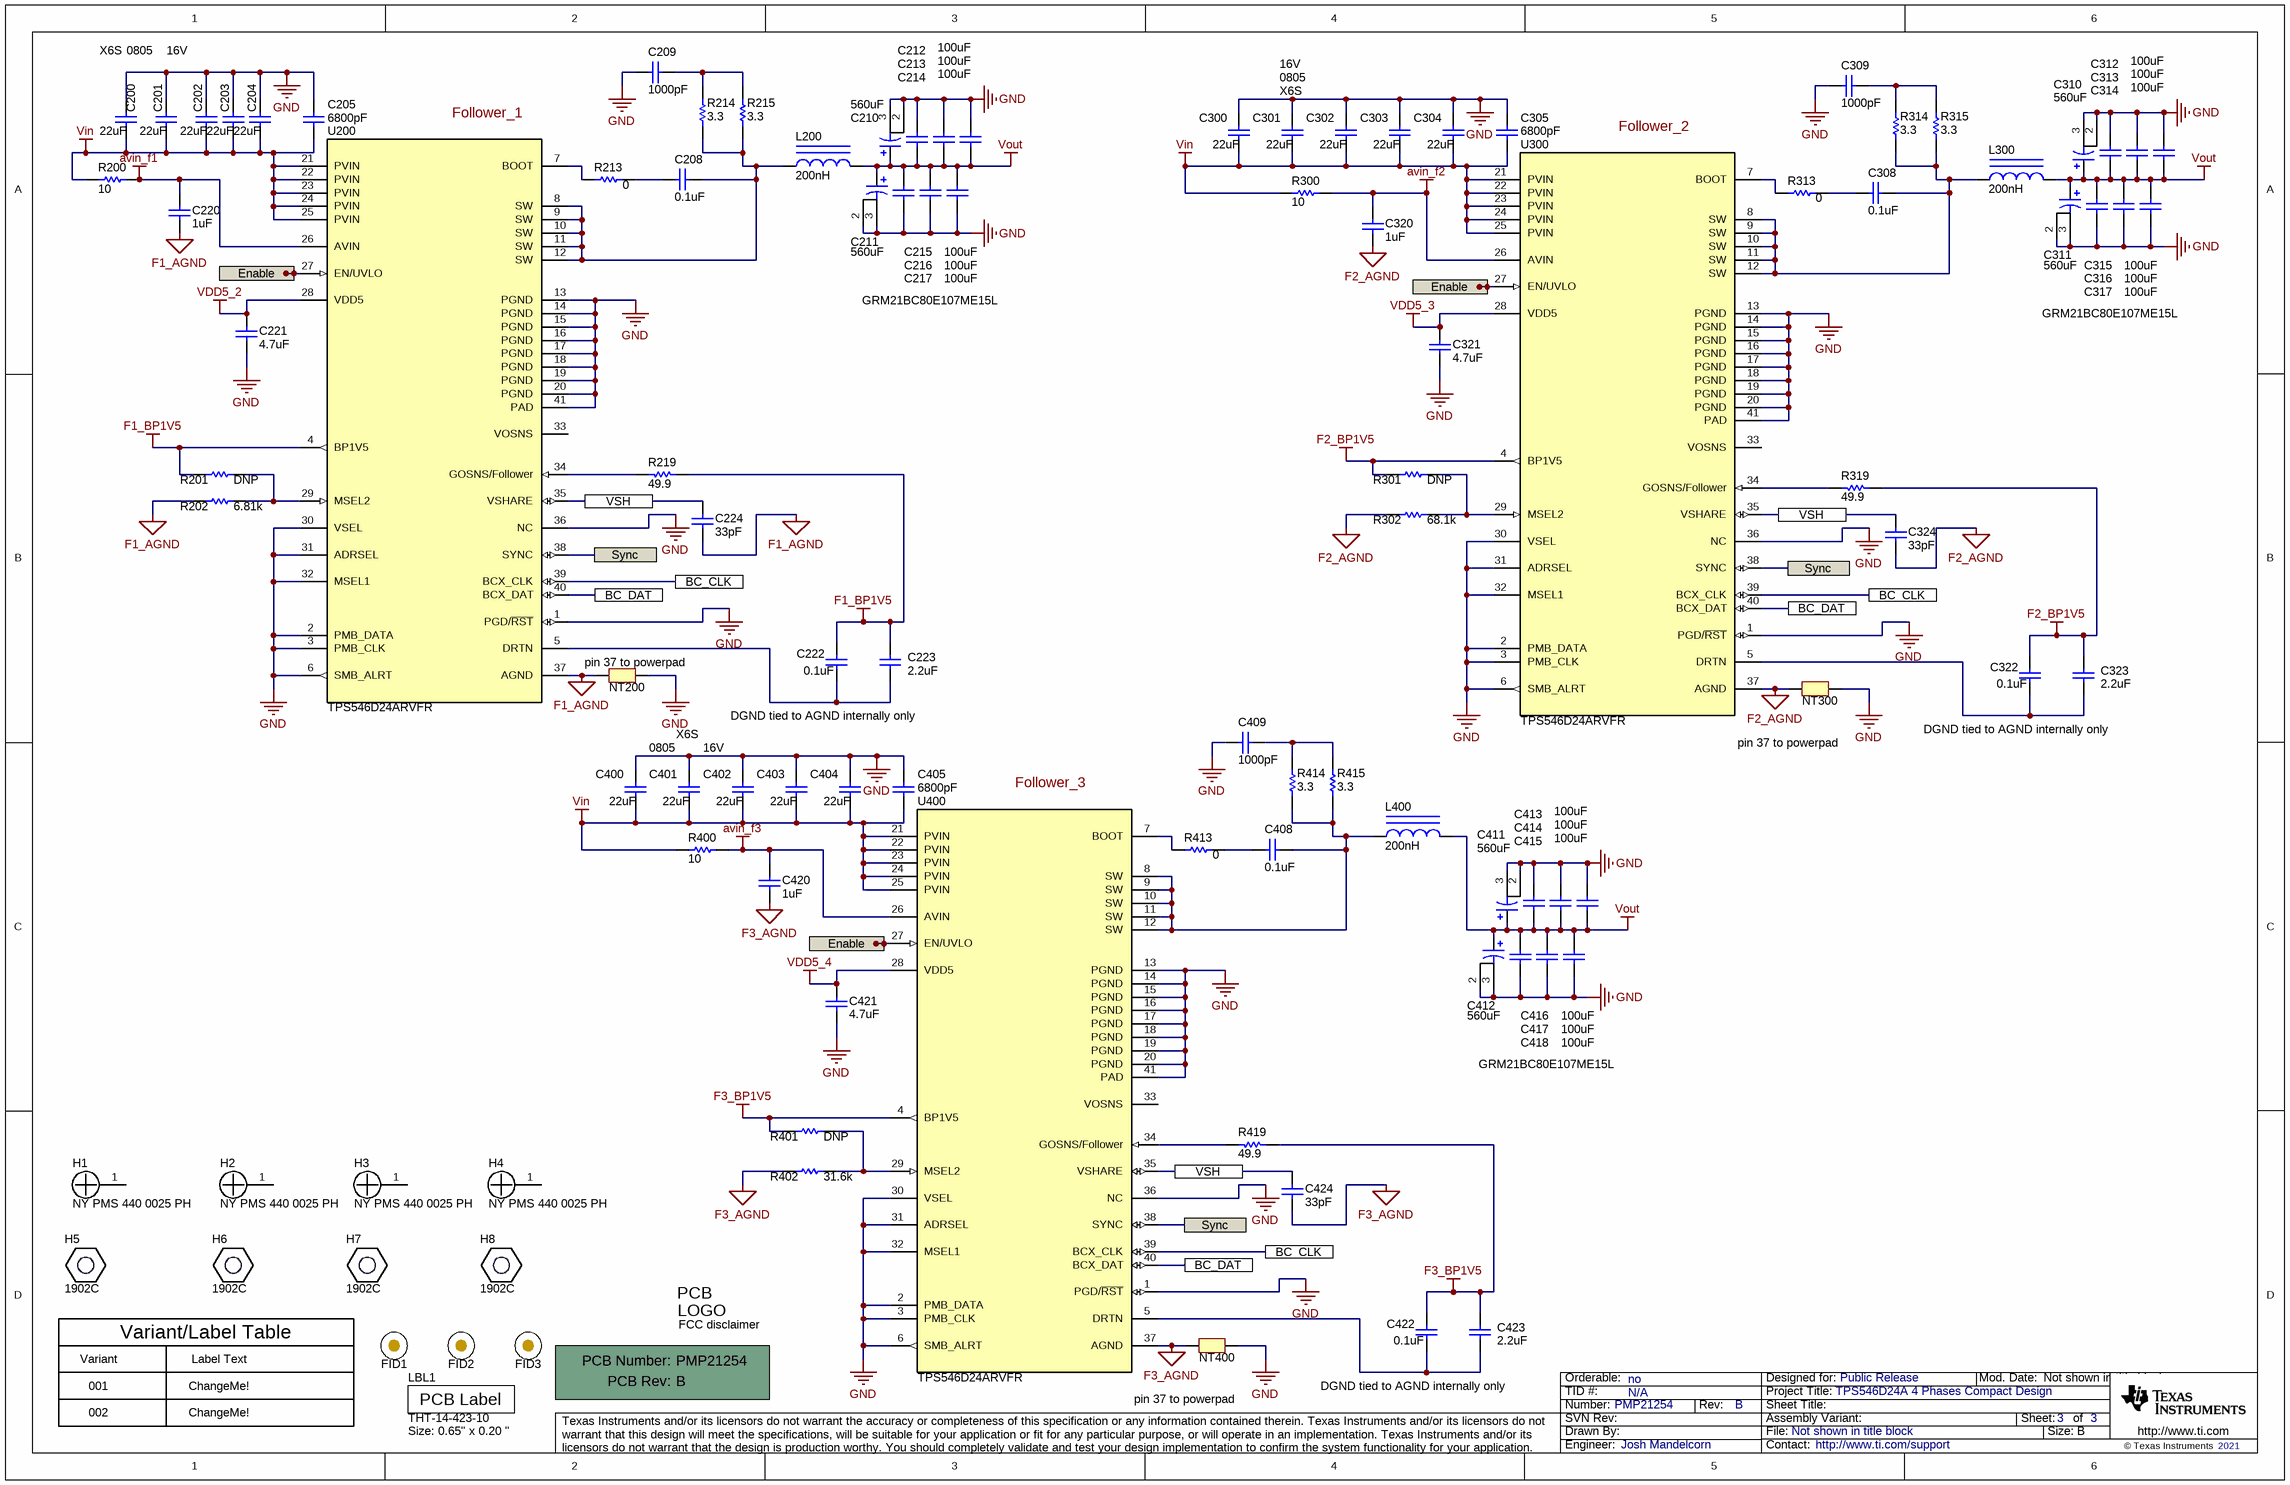
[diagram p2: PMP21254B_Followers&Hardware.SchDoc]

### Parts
!PCB1  Printed Circuit Board  (value not drawn)  (mechanical)
C200  value 22uF  [0805]  (hidden comment: Capacitor)
C201  value 22uF  VDC_V: 16V  TempCo: X6S  [0805]  (hidden comment: Capacitor)
C202  value 22uF  [0805]  (hidden comment: Capacitor)
C203  value 22uF  [0805]  (hidden comment: Capacitor)
C204  value 22uF  [0805]  (hidden comment: Capacitor)
C205  ValueDisplayed: 6800pF  [0402]  (hidden comment: Capacitor)
C208  ValueDisplayed: 0.1uF  [0402_065]  (hidden comment: Capacitor)
C209  ValueDisplayed: 1000pF  [0603L]  (hidden comment: Capacitor)
C210  ValueDisplayed: 560uF  [GX_3TERM]  (hidden comment: CAPP_POS1NEG23)
C211  ValueDisplayed: 560uF  [GX_3TERM]  (hidden comment: CAPP_POS1NEG23)
C212  ValueDisplayed: 100uF  [0805]  (hidden comment: Capacitor)
C213  ValueDisplayed: 100uF  [0805]  (hidden comment: Capacitor)
C214  ValueDisplayed: 100uF  [0805]  (hidden comment: Capacitor)
C215  ValueDisplayed: 100uF  [0805]  (hidden comment: Capacitor)
C216  ValueDisplayed: 100uF  [0805]  (hidden comment: Capacitor)
C217  ValueDisplayed: 100uF  [0805]  (hidden comment: Capacitor)
C220  ValueDisplayed: 1uF  [0603L]  (hidden comment: Capacitor)
C221  ValueDisplayed: 4.7uF  [0603]  (hidden comment: Capacitor)
C222  ValueDisplayed: 0.1uF  [0402_065]  (hidden comment: Capacitor)
C223  ValueDisplayed: 2.2uF  [0603L]  (hidden comment: Capacitor)
C224  ValueDisplayed: 33pF  [0402]  (hidden comment: Capacitor)
C300  value 22uF  [0805]  (hidden comment: Capacitor)
C301  value 22uF  VDC_V: 16V  TempCo: X6S  [0805]  (hidden comment: Capacitor)
C302  value 22uF  [0805]  (hidden comment: Capacitor)
C303  value 22uF  [0805]  (hidden comment: Capacitor)
C304  value 22uF  [0805]  (hidden comment: Capacitor)
C305  ValueDisplayed: 6800pF  [0402]  (hidden comment: Capacitor)
C308  ValueDisplayed: 0.1uF  [0402_065]  (hidden comment: Capacitor)
C309  ValueDisplayed: 1000pF  [0603L]  (hidden comment: Capacitor)
C310  ValueDisplayed: 560uF  [GX_3TERM]  (hidden comment: CAPP_POS1NEG23)
C311  ValueDisplayed: 560uF  [GX_3TERM]  (hidden comment: CAPP_POS1NEG23)
C312  ValueDisplayed: 100uF  [0805]  (hidden comment: Capacitor)
C313  ValueDisplayed: 100uF  [0805]  (hidden comment: Capacitor)
C314  ValueDisplayed: 100uF  [0805]  (hidden comment: Capacitor)
C315  ValueDisplayed: 100uF  [0805]  (hidden comment: Capacitor)
C316  ValueDisplayed: 100uF  [0805]  (hidden comment: Capacitor)
C317  ValueDisplayed: 100uF  [0805]  (hidden comment: Capacitor)
C320  ValueDisplayed: 1uF  [0603L]  (hidden comment: Capacitor)
C321  ValueDisplayed: 4.7uF  [0603]  (hidden comment: Capacitor)
C322  ValueDisplayed: 0.1uF  [0402_065]  (hidden comment: Capacitor)
C323  ValueDisplayed: 2.2uF  [0603L]  (hidden comment: Capacitor)
C324  ValueDisplayed: 33pF  [0402]  (hidden comment: Capacitor)
C400  value 22uF  [0805]  (hidden comment: Capacitor)
C401  value 22uF  VDC_V: 16V  TempCo: X6S  [0805]  (hidden comment: Capacitor)
C402  value 22uF  [0805]  (hidden comment: Capacitor)
C403  value 22uF  [0805]  (hidden comment: Capacitor)
C404  value 22uF  [0805]  (hidden comment: Capacitor)
C405  ValueDisplayed: 6800pF  [0402]  (hidden comment: Capacitor)
C408  ValueDisplayed: 0.1uF  [0402_065]  (hidden comment: Capacitor)
C409  ValueDisplayed: 1000pF  [0603L]  (hidden comment: Capacitor)
C411  ValueDisplayed: 560uF  [GX_3TERM]  (hidden comment: CAPP_POS1NEG23)
C412  ValueDisplayed: 560uF  [GX_3TERM]  (hidden comment: CAPP_POS1NEG23)
C413  ValueDisplayed: 100uF  [0805]  (hidden comment: Capacitor)
C414  ValueDisplayed: 100uF  [0805]  (hidden comment: Capacitor)
C415  ValueDisplayed: 100uF  [0805]  (hidden comment: Capacitor)
C416  ValueDisplayed: 100uF  [0805]  (hidden comment: Capacitor)
C417  ValueDisplayed: 100uF  [0805]  (hidden comment: Capacitor)
C418  ValueDisplayed: 100uF  [0805]  (hidden comment: Capacitor)
C420  ValueDisplayed: 1uF  [0603L]  (hidden comment: Capacitor)
C421  ValueDisplayed: 4.7uF  [0603]  (hidden comment: Capacitor)
C422  ValueDisplayed: 0.1uF  [0402_065]  (hidden comment: Capacitor)
C423  ValueDisplayed: 2.2uF  [0603L]  (hidden comment: Capacitor)
C424  ValueDisplayed: 33pF  [0402]  (hidden comment: Capacitor)
FID1  Fiducial  [Fiducial10-20]  (value not drawn)
FID2  Fiducial  [Fiducial10-20]  (value not drawn)
FID3  Fiducial  [Fiducial10-20]  (value not drawn)
H1  NY PMS 440 0025 PH  [NY PMS 440 0025 PH]
H2  NY PMS 440 0025 PH  [NY PMS 440 0025 PH]
H3  NY PMS 440 0025 PH  [NY PMS 440 0025 PH]
H4  NY PMS 440 0025 PH  [NY PMS 440 0025 PH]
H5  1902C  [Keystone_1902C]
H6  1902C  [Keystone_1902C]
H7  1902C  [Keystone_1902C]
H8  1902C  [Keystone_1902C]
L200  ValueDisplayed: 200nH  [SLC1480]  (hidden comment: Inductor_Iron)
L300  ValueDisplayed: 200nH  [SLC1480]  (hidden comment: Inductor_Iron)
L400  ValueDisplayed: 200nH  [SLC1480]  (hidden comment: Inductor_Iron)
LBL1  THT-14-423-10  Note: Size: 0.65" x 0.20 "  [Label_650x200]
Logo2  FCC disclaimer  [FCC_disclaimer]  (no BOM)
NT200  Net-Tie  [Net-Tie_10mil]  (value not drawn)  (net tie, no BOM)
NT300  Net-Tie  [Net-Tie_10mil]  (value not drawn)  (net tie, no BOM)
NT400  Net-Tie  [Net-Tie_10mil]  (value not drawn)  (net tie, no BOM)
R200  ValueDisplayed: 10  [0402]  (hidden comment: CRCW040210R0JNED)
R201  ValueDisplayed: DNP  [0402]  (hidden comment: Resistor)
R202  ValueDisplayed: 6.81k  [0402]  (hidden comment: Resistor)
R213  ValueDisplayed: 0  [0402]  (hidden comment: Resistor)
R214  ValueDisplayed: 3.3  [0805]  (hidden comment: Resistor)
R215  ValueDisplayed: 3.3  [0805]  (hidden comment: Resistor)
R219  ValueDisplayed: 49.9  [0402]  (hidden comment: Resistor)
R300  ValueDisplayed: 10  [0402]  (hidden comment: CRCW040210R0JNED)
R301  ValueDisplayed: DNP  [0402]  (hidden comment: Resistor)
R302  ValueDisplayed: 68.1k  [0402]  (hidden comment: Resistor)
R313  ValueDisplayed: 0  [0402]  (hidden comment: Resistor)
R314  ValueDisplayed: 3.3  [0805]  (hidden comment: Resistor)
R315  ValueDisplayed: 3.3  [0805]  (hidden comment: Resistor)
R319  ValueDisplayed: 49.9  [0402]  (hidden comment: Resistor)
R400  ValueDisplayed: 10  [0402]  (hidden comment: CRCW040210R0JNED)
R401  ValueDisplayed: DNP  [0402]  (hidden comment: Resistor)
R402  ValueDisplayed: 31.6k  [0402]  (hidden comment: Resistor)
R413  ValueDisplayed: 0  [0402]  (hidden comment: Resistor)
R414  ValueDisplayed: 3.3  [0805]  (hidden comment: Resistor)
R415  ValueDisplayed: 3.3  [0805]  (hidden comment: Resistor)
R419  ValueDisplayed: 49.9  [0402]  (hidden comment: Resistor)
U200  TPS546D24ARVFR  [RVF0040A_SMD_NV]
U300  TPS546D24ARVFR  [RVF0040A_SMD_NV]
U400  TPS546D24ARVFR  [RVF0040A_SMD_NV]

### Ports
BC_CLK, BC_DAT, Enable, Sync, VSH

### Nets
avin_f1: C220.1 R200.2 U200.26(AVIN)
avin_f2: C320.1 R300.2 U300.26(AVIN)
avin_f3: C420.1 R400.2 U400.26(AVIN)
F1_AGND: C220.2 C224.2 NT200.1 R202.1 U200.37(AGND)
F1_BP1V5: C222.1 C223.1 R201.1 R219.1 U200.4(BP1V5)
F2_AGND: C320.2 C324.2 NT300.1 R302.1 U300.37(AGND)
F2_BP1V5: C322.1 C323.1 R301.1 R319.1 U300.4(BP1V5)
F3_AGND: C420.2 C424.2 NT400.1 R402.1 U400.37(AGND)
F3_BP1V5: C422.1 C423.1 R401.1 R419.1 U400.4(BP1V5)
GND: C200.2 C201.1 C202.1 C203.1 C204.1 C205.2 C209.2 C210.2(-) C210.3(-) C211.2(-) C211.3(-) C212.2 C213.2 C214.2 C215.2 C216.2 C217.2 C221.1 C300.2 C301.1 C302.1 C303.1 C304.1 C305.2 C309.2 C310.2(-) C310.3(-) C311.2(-) C311.3(-) C312.2 C313.2 C314.2 C315.2 C316.2 C317.2 C321.1 C400.2 C401.1 C402.1 C403.1 C404.1 C405.2 C409.2 C411.2(-) C411.3(-) C412.2(-) C412.3(-) C413.2 C414.2 C415.2 C416.2 C417.2 C418.2 C421.1 NT200.2 NT300.2 NT400.2 U200.1(PGD/~{RST}) U200.2(PMB_DATA) U200.3(PMB_CLK) U200.6(SMB_ALRT) U200.13(PGND) U200.14(PGND) U200.15(PGND) U200.16(PGND) U200.17(PGND) U200.18(PGND) U200.19(PGND) U200.20(PGND) U200.30(VSEL) U200.31(ADRSEL) U200.32(MSEL1) U200.36(NC) U200.41(PAD) U300.1(PGD/~{RST}) U300.2(PMB_DATA) U300.3(PMB_CLK) U300.6(SMB_ALRT) U300.13(PGND) U300.14(PGND) U300.15(PGND) U300.16(PGND) U300.17(PGND) U300.18(PGND) U300.19(PGND) U300.20(PGND) U300.30(VSEL) U300.31(ADRSEL) U300.32(MSEL1) U300.36(NC) U300.41(PAD) U400.1(PGD/~{RST}) U400.2(PMB_DATA) U400.3(PMB_CLK) U400.6(SMB_ALRT) U400.13(PGND) U400.14(PGND) U400.15(PGND) U400.16(PGND) U400.17(PGND) U400.18(PGND) U400.19(PGND) U400.20(PGND) U400.30(VSEL) U400.31(ADRSEL) U400.32(MSEL1) U400.36(NC) U400.41(PAD)
VDD5_2: C221.2 U200.28(VDD5)
VDD5_3: C321.2 U300.28(VDD5)
VDD5_4: C421.2 U400.28(VDD5)
Vin: C200.1 C201.2 C202.2 C203.2 C204.2 C205.1 C300.1 C301.2 C302.2 C303.2 C304.2 C305.1 C400.1 C401.2 C402.2 C403.2 C404.2 C405.1 R200.1 R300.1 R400.1 U200.21(PVIN) U200.22(PVIN) U200.23(PVIN) U200.24(PVIN) U200.25(PVIN) U300.21(PVIN) U300.22(PVIN) U300.23(PVIN) U300.24(PVIN) U300.25(PVIN) U400.21(PVIN) U400.22(PVIN) U400.23(PVIN) U400.24(PVIN) U400.25(PVIN)
Vout: C210.1(+) C211.1(+) C212.1 C213.1 C214.1 C215.1 C216.1 C217.1 C310.1(+) C311.1(+) C312.1 C313.1 C314.1 C315.1 C316.1 C317.1 C411.1(+) C412.1(+) C413.1 C414.1 C415.1 C416.1 C417.1 C418.1 L200.2 L300.2 L400.2
BC_CLK: U200.39(BCX_CLK) U300.39(BCX_CLK) U400.39(BCX_CLK) ; port BC_CLK
BC_DAT: U200.40(BCX_DAT) U300.40(BCX_DAT) U400.40(BCX_DAT) ; port BC_DAT
Enable: U200.27(EN/UVLO) U300.27(EN/UVLO) U400.27(EN/UVLO) ; port Enable
Sync: U200.38(SYNC) U300.38(SYNC) U400.38(SYNC) ; port Sync
VSH: C224.1 C324.1 C424.1 U200.35(VSHARE) U300.35(VSHARE) U400.35(VSHARE) ; port VSH
NetC208_1: C208.1 R213.1
NetC208_2: C208.2 L200.1 R214.1 R215.1 U200.8(SW) U200.9(SW) U200.10(SW) U200.11(SW) U200.12(SW)
NetC209_1: C209.1 R214.2 R215.2
NetC222_2: C222.2 C223.2 U200.5(DRTN)
NetC308_1: C308.1 R313.1
NetC308_2: C308.2 L300.1 R314.1 R315.1 U300.8(SW) U300.9(SW) U300.10(SW) U300.11(SW) U300.12(SW)
NetC309_1: C309.1 R314.2 R315.2
NetC322_2: C322.2 C323.2 U300.5(DRTN)
NetC408_1: C408.1 R413.1
NetC408_2: C408.2 L400.1 R414.1 R415.1 U400.8(SW) U400.9(SW) U400.10(SW) U400.11(SW) U400.12(SW)
NetC409_1: C409.1 R414.2 R415.2
NetC422_2: C422.2 C423.2 U400.5(DRTN)
NetR201_2: R201.2 R202.2 U200.29(MSEL2)
NetR213_2: R213.2 U200.7(BOOT)
NetR219_2: R219.2 U200.34(GOSNS/Follower)
NetR301_2: R301.2 R302.2 U300.29(MSEL2)
NetR313_2: R313.2 U300.7(BOOT)
NetR319_2: R319.2 U300.34(GOSNS/Follower)
NetR401_2: R401.2 R402.2 U400.29(MSEL2)
NetR413_2: R413.2 U400.7(BOOT)
NetR419_2: R419.2 U400.34(GOSNS/Follower)

Not connected (* = marked no-connect by the designer): H1 1; H2 1; H3 1; H4 1; U200 33(VOSNS); U300 33(VOSNS); U400 33(VOSNS)

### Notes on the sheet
- (near U200) Follower_1
- (near U300) Follower_2
- GRM21BC80E107ME15L
- (near NT200) pin 37 to powerpad
- DGND tied to AGND internally only
- pin 37 to powerpad
- (near U400) Follower_3
- Variant
- Variant/Label Table
- Label Text
- 001
- 002
- ChangeMe!

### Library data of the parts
!PCB1 = CMP-0003618-2: Manufacturer: Any; PartNumber: PMP21254
C200 C202-C204 C300 C302-C304 C400 C402-C404 = CMP-0007852-1: as C3 on sheet PMP21254B_Leader&Aux
C201 C301 C401 = CMP-0007852-1: as C101 on sheet PMP21254B_Leader&Aux
C205 C305 C405 = CMP-0006696-2: as C105 on sheet PMP21254B_Leader&Aux
C208 C222 C308 C322 C408 C422 = CMP-0006204-2: as C7 on sheet PMP21254B_Leader&Aux
C209 C309 C409 = CMP-0006723-4: as C109 on sheet PMP21254B_Leader&Aux
C210 C211 C310 C311 C411 C412 = CMP-0012239-3: as C110 on sheet PMP21254B_Leader&Aux
C212-C217 C312-C317 C413-C418 = CMP-0008277-2: as C112 on sheet PMP21254B_Leader&Aux
C220 C320 C420 = CMP-0007405-4: as C120 on sheet PMP21254B_Leader&Aux
C221 C321 C421 = CMP-0007058-4: as C121 on sheet PMP21254B_Leader&Aux
C223 C323 C423 = CMP-0007499-4: as C123 on sheet PMP21254B_Leader&Aux
C224 C324 C424 = CMP-0006377-2: as C124 on sheet PMP21254B_Leader&Aux
FID1-FID3 = CMP-0077181-1: Fiducial mark.  There is nothing to buy or mount.
H1-H4 = CMP-0003617-1: Machine Screw, Round, #4-40 x 1/4, Nylon, Philips panhead; Manufacturer: B&F Fastener Supply; CompType: Hardware
H5-H8 = CMP-0003610-1: Standoff, Hex, 0.5"L #4-40 Nylon; Manufacturer: Keystone; CompType: Hardware
L200 L300 L400 = CMP-0060886-1: Inductor, Shielded, Ferrite, 200 nH, 55 A, 0.00015 ohm, SMD; PartNumber: SLC1480-201MLB; Manufacturer: Coilcraft; Value: 200nH; Imax_A: 55A; Irms: 55A @ 40C rise; Isat: 76A @ 30% inductance drop; DCR_ohm: 150µ; SizeAreaWB_mm2: 231.127; SizeArea_mm2: 174.307; SizeX_mm: 13.46; SizeY_mm: 12.95; SizeZ_mm: 8; AEC Category: Q200; Green_Lifecycle: Not Set; Green_REACh: Incomplete
LBL1 = CMP-0003625-1: Thermal Transfer Printable Labels, 0.650" W x 0.200" H - 10,000 per roll; Manufacturer: Brady; CompType: Label
Logo2 = CMP-0074847-1: FCC_disclaimer; Library Reference: Logo
NT200 NT300 NT400 = CMP-0078142-3: Single point connection between nets.
R200 R300 R400 = CMP-0026827-3: as R100 on sheet PMP21254B_Leader&Aux
R201 R202 R301 R302 R401 R402 = CMP-0025958-3: as R101 on sheet PMP21254B_Leader&Aux
R213 R313 R413 = CMP-0026822-3: as R113 on sheet PMP21254B_Leader&Aux
R214 R215 R314 R315 R414 R415 = CMP-0020547-3: as R114 on sheet PMP21254B_Leader&Aux
R219 R319 R419 = CMP-0026404-2: as R12 on sheet PMP21254B_Leader&Aux
U200 U300 U400 = CMP-0860534-2: as U100 on sheet PMP21254B_Leader&Aux

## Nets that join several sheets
avin_f1: PMP21254B_Leader&Aux (J1.4), PMP21254B_Followers&Hardware (C220.1 R200.2 U200.26)
avin_f2: PMP21254B_Leader&Aux (J1.6), PMP21254B_Followers&Hardware (C320.1 R300.2 U300.26)
avin_f3: PMP21254B_Leader&Aux (J1.8), PMP21254B_Followers&Hardware (C420.1 R400.2 U400.26)
GND: PMP21254B_Leader&Aux (64 pins), PMP21254B_Followers&Hardware (108 pins)
Vin: PMP21254B_Leader&Aux (18 pins), PMP21254B_Followers&Hardware (36 pins)
Vout: PMP21254B_Leader&Aux (23 pins), PMP21254B_Followers&Hardware (27 pins)
BC_CLK: PMP21254B_Leader&Aux (U100.39), PMP21254B_Followers&Hardware (U200.39 U300.39 U400.39)
BC_DAT: PMP21254B_Leader&Aux (U100.40), PMP21254B_Followers&Hardware (U200.40 U300.40 U400.40)
Enable: PMP21254B_Leader&Aux (J3.2 J3.4 J3.6 U100.27), PMP21254B_Followers&Hardware (U200.27 U300.27 U400.27)
Sync: PMP21254B_Leader&Aux (U100.38), PMP21254B_Followers&Hardware (U200.38 U300.38 U400.38)
VSH: PMP21254B_Leader&Aux (C124.1 U100.35), PMP21254B_Followers&Hardware (6 pins)

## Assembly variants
001: not fitted FID1 FID2 FID3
